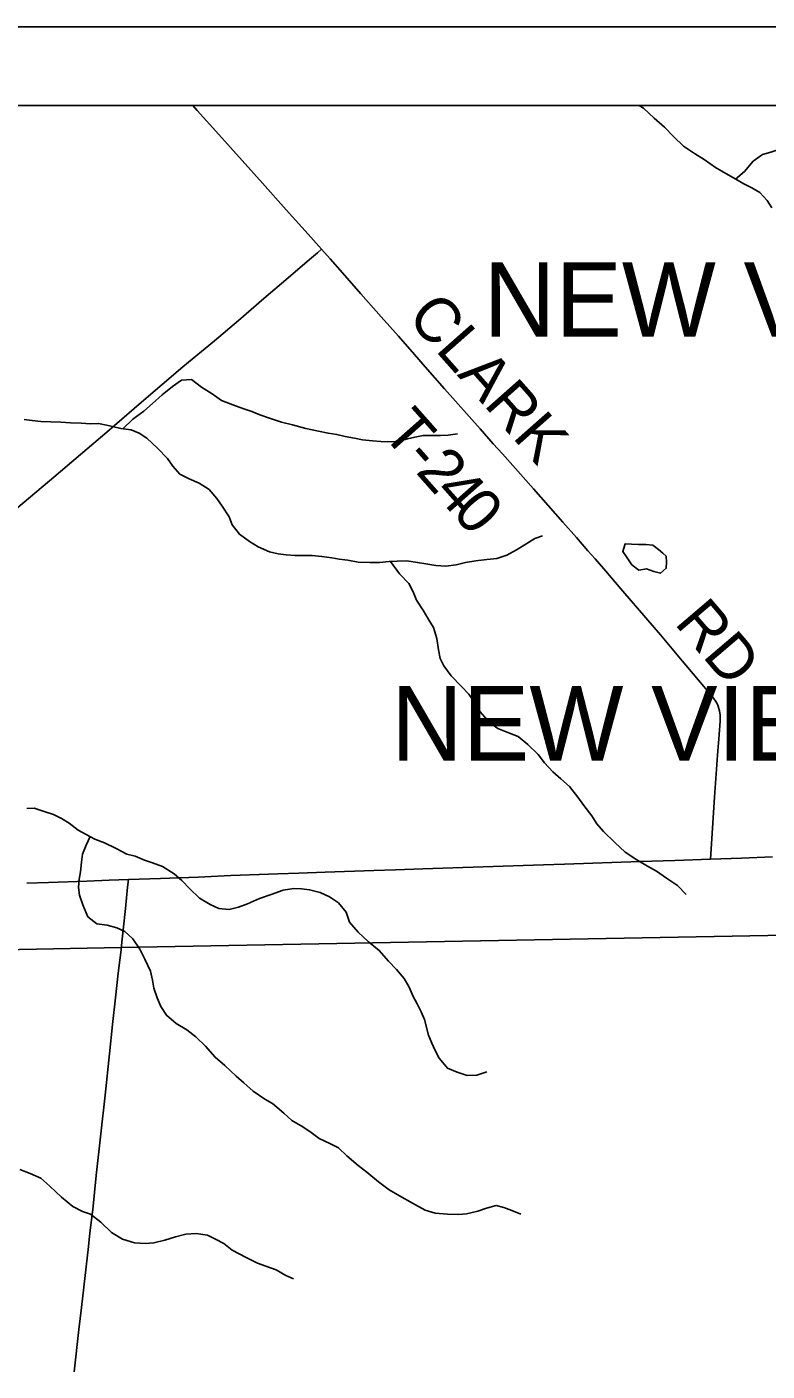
# Model space of a CAD drawing. Extents: x 0 to 48.6, y 0 to 22.
# Drawn here: x 7.09 to 8.031, y 19.291 to 21 of the extents above; entities that cross this region are included whole.
import ezdxf

# ---------------------------------------------------------------- set-up
doc = ezdxf.new("R2010")
doc.units = 0
for name, color, linetype in [('GM_X_Corporation', 7, 'Continuous'), ('GM_X_Corporation_Text', 7, 'Continuous'), ('GM_X_Major_River', 7, 'Continuous'), ('GM_X_Minor_Lake', 7, 'Continuous'), ('GM_X_Minor_River', 7, 'Continuous'), ('GM_X_Rail_Line', 7, 'Continuous'), ('GM_X_State_Route', 7, 'Continuous'), ('GM_X_Township_Road', 7, 'Continuous'), ('GM_X_Township_Road_Text', 7, 'Continuous'), ('SH_Data', 7, 'Continuous')]:
    doc.layers.add(name, color=color, linetype=linetype)

msp = doc.modelspace()

# ---------------------------------------------------------------- linework, layer by layer
at = {"layer": 'GM_X_Corporation'}
msp.add_lwpolyline([(6.9471, 18.0777), (7.2261, 18.2847), (8.5348, 19.2897), (8.9, 19.5692), (8.9, 20.9), (2.1, 20.9)], dxfattribs=at)
msp.add_lwpolyline([(8.9, 19.5692), (8.9, 20.9), (5.795, 20.9), (5.8236, 20.7829), (6.0412, 19.8859), (6.2759, 18.9159), (6.3396, 18.6531), (6.4996, 17.9212), (6.5365, 17.7727), (6.9471, 18.0777), (7.2261, 18.2847), (8.5348, 19.2897)], close=True, dxfattribs=at)
at = {"layer": 'GM_X_Major_River'}
msp.add_lwpolyline([(7.868, 20.9), (7.8738, 20.8966), (7.8873, 20.8839), (7.9004, 20.8723), (7.912, 20.8604), (7.9247, 20.8485), (7.9386, 20.8388), (7.9506, 20.8315), (7.9653, 20.821), (7.9784, 20.8137), (7.9909, 20.8063), (8.0014, 20.8005), (8.0112, 20.7954), (8.0217, 20.7896), (8.0307, 20.7792), (8.0366, 20.7697)], dxfattribs=at)
at = {"layer": 'GM_X_Minor_Lake'}
for points in [[(7.8982, 20.3308), (7.8929, 20.3356), (7.8854, 20.3409), (7.8766, 20.3418), (7.8675, 20.3419), (7.8584, 20.3423), (7.8505, 20.3428), (7.8473, 20.3329), (7.852, 20.3261)], [(7.852, 20.3261), (7.8589, 20.3158), (7.8676, 20.3092), (7.8775, 20.311), (7.887, 20.3075), (7.8953, 20.3052), (7.9025, 20.3116), (7.903, 20.3192), (7.9023, 20.3271), (7.8982, 20.3308)]]:
    msp.add_lwpolyline(points, dxfattribs=at)
at = {"layer": 'GM_X_Minor_River'}
for points in [[(7.9905, 20.8065), (8.002, 20.8162), (8.0131, 20.8294), (8.0249, 20.8376), (8.0356, 20.8406), (8.0478, 20.845), (8.0577, 20.8487), (8.0679, 20.8532), (8.0778, 20.8565), (8.0885, 20.8598), (8.1022, 20.8639), (8.114, 20.868), (8.1254, 20.8728), (8.1369, 20.8791), (8.1483, 20.8847), (8.1601, 20.893), (8.1675, 20.9)], [(7.212, 20.489), (7.2247, 20.501), (7.2384, 20.5115), (7.2495, 20.5209), (7.2618, 20.5322), (7.2748, 20.5427), (7.2862, 20.5509), (7.2991, 20.5516), (7.3119, 20.542), (7.3255, 20.5335), (7.3372, 20.525), (7.3516, 20.5192), (7.3644, 20.5149), (7.3758, 20.511), (7.386, 20.5068), (7.3981, 20.5025), (7.4136, 20.4974), (7.4276, 20.4939), (7.4446, 20.4892), (7.4605, 20.486), (7.4727, 20.4832), (7.4837, 20.4816), (7.4946, 20.4792), (7.5064, 20.4768), (7.5166, 20.4748), (7.5291, 20.4736), (7.5397, 20.4727), (7.553, 20.4722), (7.5625, 20.4733), (7.5735, 20.4762), (7.583, 20.4784), (7.5937, 20.4802), (7.6043, 20.4805), (7.6157, 20.4804), (7.6252, 20.4807), (7.6373, 20.4825)], [(7.0865, 20.5008), (7.0964, 20.4995), (7.1074, 20.4983), (7.1203, 20.4978), (7.1328, 20.4973), (7.1453, 20.4964), (7.159, 20.4959), (7.1707, 20.4954), (7.181, 20.4957), (7.1931, 20.4933), (7.2094, 20.4894), (7.2223, 20.4874), (7.2325, 20.4835), (7.2423, 20.4769), (7.2558, 20.4643), (7.2686, 20.4513), (7.2754, 20.4414), (7.2844, 20.4314), (7.2961, 20.4252), (7.3089, 20.4198), (7.3214, 20.4117), (7.3311, 20.4002), (7.3379, 20.3907), (7.3469, 20.3769), (7.3509, 20.3667), (7.36, 20.3548), (7.3728, 20.3456), (7.3837, 20.339), (7.3981, 20.3325), (7.4091, 20.3301), (7.4193, 20.3288), (7.4307, 20.328), (7.4527, 20.3278), (7.4648, 20.3265), (7.4773, 20.3249), (7.4868, 20.3233), (7.4978, 20.3217), (7.511, 20.3193), (7.5258, 20.3188), (7.538, 20.319), (7.5505, 20.3201), (7.5607, 20.3207), (7.5729, 20.321), (7.5865, 20.319), (7.5971, 20.317), (7.6096, 20.315), (7.6225, 20.3141), (7.6355, 20.3159), (7.6476, 20.3188), (7.6605, 20.321), (7.6746, 20.3227), (7.6871, 20.3241), (7.7001, 20.3282), (7.7123, 20.3349), (7.7218, 20.3409), (7.7356, 20.3495), (7.7454, 20.3528)], [(7.5519, 20.3202), (7.5633, 20.3044), (7.5753, 20.2921), (7.5809, 20.2815), (7.5853, 20.2708), (7.5939, 20.2574), (7.5999, 20.2471), (7.6067, 20.2364), (7.6111, 20.2224), (7.6129, 20.2079), (7.615, 20.1969), (7.6199, 20.1874), (7.6293, 20.1747), (7.642, 20.1617), (7.6518, 20.1514), (7.6586, 20.1415), (7.666, 20.1289), (7.6777, 20.1155), (7.6886, 20.1078), (7.7034, 20.102), (7.7143, 20.0977), (7.7267, 20.0873), (7.7399, 20.0747), (7.7478, 20.064), (7.7583, 20.0529), (7.7685, 20.0437), (7.7798, 20.0341), (7.7903, 20.0203), (7.7978, 20.01), (7.8079, 19.9966), (7.8143, 19.9867), (7.8229, 19.9768), (7.8372, 19.963), (7.8504, 19.9507), (7.8651, 19.9407), (7.8787, 19.9326), (7.8904, 19.9264), (7.9028, 19.9176), (7.9168, 19.908), (7.928, 19.8965)], [(7.0897, 20.0062), (7.0992, 20.0065), (7.112, 20.0022), (7.1238, 19.9983), (7.134, 19.9933), (7.1438, 19.9875), (7.1551, 19.9783), (7.1653, 19.9729), (7.1762, 19.9671), (7.1887, 19.9624), (7.2034, 19.9554), (7.2167, 19.9481), (7.2276, 19.9453), (7.2394, 19.9403), (7.2496, 19.9368), (7.2624, 19.9325), (7.2772, 19.9229), (7.2869, 19.9144), (7.2971, 19.9041), (7.3091, 19.8922), (7.3227, 19.8841), (7.3337, 19.8791), (7.3469, 19.8775), (7.3587, 19.8808), (7.3702, 19.8848), (7.3854, 19.8915), (7.4002, 19.8967), (7.4155, 19.9023), (7.4291, 19.9044), (7.439, 19.904), (7.4492, 19.9027), (7.4625, 19.8992), (7.4746, 19.8938), (7.4859, 19.8861), (7.4957, 19.8742), (7.5001, 19.8617), (7.511, 19.8487), (7.5242, 19.8364), (7.5377, 19.8256), (7.5497, 19.8119), (7.5595, 19.8012), (7.5693, 19.7897), (7.5756, 19.779), (7.5808, 19.7672), (7.5861, 19.7576), (7.5909, 19.7477), (7.5954, 19.7378), (7.6005, 19.718), (7.6046, 19.7078), (7.6087, 19.6982), (7.6139, 19.6887), (7.6244, 19.6757), (7.6369, 19.6706), (7.6494, 19.6667), (7.6619, 19.667), (7.6745, 19.6711)], [(7.1701, 19.9703), (7.1652, 19.9596), (7.1605, 19.9478), (7.1593, 19.938), (7.158, 19.9255), (7.1564, 19.916), (7.1556, 19.9054), (7.1566, 19.8959), (7.1611, 19.8837), (7.1674, 19.8685), (7.1787, 19.8596), (7.192, 19.8576), (7.2044, 19.8545), (7.2143, 19.8498), (7.2244, 19.8402), (7.2334, 19.8273), (7.2398, 19.8143), (7.2472, 19.7994), (7.2494, 19.7876), (7.2512, 19.7778), (7.2556, 19.7652), (7.2601, 19.7541), (7.2672, 19.7431), (7.2796, 19.7327), (7.2932, 19.7246), (7.3045, 19.7158), (7.3169, 19.7039), (7.329, 19.6898), (7.3414, 19.6794), (7.3557, 19.6656), (7.3658, 19.6572), (7.3775, 19.6464), (7.3922, 19.6364), (7.402, 19.631), (7.4164, 19.6187), (7.4265, 19.6095), (7.4405, 19.6014), (7.4514, 19.5941), (7.4616, 19.5865), (7.4748, 19.5799), (7.4858, 19.5745), (7.4967, 19.5645), (7.511, 19.5522), (7.5219, 19.5438), (7.537, 19.5315), (7.5502, 19.5211), (7.5634, 19.5134), (7.58, 19.5042), (7.5963, 19.4953), (7.6087, 19.4914), (7.6247, 19.4901), (7.6387, 19.4896), (7.6486, 19.4906), (7.663, 19.4939), (7.6741, 19.498), (7.6862, 19.5013), (7.6961, 19.4986), (7.7063, 19.495), (7.7176, 19.4904)], [(7.0811, 19.547), (7.0939, 19.542), (7.1075, 19.5361), (7.1192, 19.5258), (7.1339, 19.512), (7.1482, 19.5001), (7.1606, 19.4935), (7.1709, 19.49), (7.184, 19.48), (7.1976, 19.467), (7.2112, 19.4585), (7.2267, 19.4538), (7.2403, 19.453), (7.2514, 19.4536), (7.2654, 19.4573), (7.2787, 19.4613), (7.2917, 19.4646), (7.305, 19.4657), (7.3194, 19.4633), (7.3296, 19.4586), (7.3401, 19.4528), (7.3507, 19.4444), (7.3684, 19.4351), (7.3832, 19.4281), (7.3938, 19.4239), (7.4066, 19.4192), (7.4191, 19.4122), (7.4289, 19.408)]]:
    msp.add_lwpolyline(points, dxfattribs=at)
at = {"layer": 'GM_X_Rail_Line'}
msp.add_lwpolyline([(2.1, 19.7643), (2.1011, 19.7645), (2.172, 19.7738), (2.2311, 19.7779), (2.3038, 19.7803), (2.4027, 19.7791), (2.7583, 19.782), (3.4579, 19.785), (4.2295, 19.785), (4.6206, 19.7852), (5.0462, 19.7937), (5.6922, 19.8043), (6.0216, 19.8102), (6.7352, 19.82), (7.2096, 19.8291), (8.1004, 19.8459), (8.9, 19.8619)], dxfattribs=at)
at = {"layer": 'GM_X_State_Route'}
msp.add_lwpolyline([(7.0896, 19.911), (7.1175, 19.912), (7.166, 19.9137), (7.1945, 19.915), (7.219, 19.9158), (7.2597, 19.9172), (7.3075, 19.9189), (7.3491, 19.9208), (7.4087, 19.9228), (7.4354, 19.9237), (7.4689, 19.9249), (7.531, 19.9274), (7.5583, 19.928), (7.5931, 19.9294), (7.708, 19.9333), (7.7465, 19.9345), (7.7732, 19.9354), (7.8694, 19.9388), (7.9135, 19.9401), (7.9587, 19.9417), (7.9981, 19.9429), (8.0378, 19.9444)], dxfattribs=at)
at = {"layer": 'GM_X_Township_Road'}
for points in [[(7.4645, 20.7172), (7.4474, 20.7365), (7.4194, 20.7673), (7.3892, 20.8011), (7.3637, 20.83), (7.3338, 20.8633), (7.3064, 20.8938), (7.3009, 20.9)], [(7.0538, 20.3683), (7.1242, 20.4276), (7.1833, 20.4779), (7.1913, 20.4848), (7.2012, 20.4933), (7.2356, 20.5229), (7.2882, 20.5675), (7.3283, 20.6009), (7.3587, 20.6265), (7.3911, 20.6545), (7.4218, 20.6808), (7.4492, 20.7042), (7.4591, 20.7127), (7.4645, 20.7172)], [(7.9587, 19.9417), (7.9641, 20.0206), (7.9677, 20.074), (7.9681, 20.0792), (7.9685, 20.0845), (7.9689, 20.0894), (7.9694, 20.0943), (7.9699, 20.1), (7.971, 20.1173), (7.9711, 20.121), (7.9711, 20.1248), (7.9704, 20.1303), (7.9692, 20.1345), (7.9681, 20.1374), (7.9669, 20.1398), (7.9655, 20.1423), (7.9626, 20.1463), (7.9588, 20.1512), (7.9503, 20.1612), (7.9366, 20.1772), (7.9227, 20.194), (7.8951, 20.2268), (7.8768, 20.2487), (7.8476, 20.2826), (7.8233, 20.3109), (7.8122, 20.3235), (7.803, 20.3336), (7.7885, 20.3506), (7.7712, 20.3701), (7.7338, 20.4125), (7.6943, 20.4572), (7.6825, 20.47), (7.6662, 20.4888), (7.6209, 20.5399), (7.5962, 20.5679), (7.5826, 20.5832), (7.5621, 20.6065), (7.5402, 20.6311), (7.5144, 20.6606), (7.491, 20.6871), (7.4755, 20.7049), (7.4645, 20.7172)], [(7.15, 19.2899), (7.1561, 19.3436), (7.1592, 19.3714), (7.1681, 19.4491), (7.17, 19.4664), (7.1735, 19.496), (7.1779, 19.5393), (7.1838, 19.5924), (7.1892, 19.6417), (7.1948, 19.6942), (7.1987, 19.7313), (7.2026, 19.7653), (7.2059, 19.7967), (7.2096, 19.8263), (7.2105, 19.8362), (7.2151, 19.8788), (7.2179, 19.9059), (7.219, 19.9158)]]:
    msp.add_lwpolyline(points, dxfattribs=at)
at = {"layer": 'SH_Data'}
for p, q in [((2, 21), (9, 21)), ((2.1, 20.9), (8.9, 20.9))]:
    msp.add_line(p, q, dxfattribs=at)

# ---------------------------------------------------------------- texts
at = {"layer": 'GM_X_Corporation_Text'}
for p in [(7.6702, 20.606), (7.5527, 20.0671)]:
    msp.add_text('NEW VIENNA', height=0.0947, rotation=0, dxfattribs=at).set_placement(p)
at = {"layer": 'GM_X_Township_Road_Text'}
for s, height, rotation, p in [('CLARK', 0.05682, 311.4833, (7.5717, 20.63)), ('T', 0.0568, 311.4785, (7.5396, 20.483)), ('-', 0.0568, 311.4787, (7.5677, 20.4512)), ('2', 0.0568, 311.4785, (7.583, 20.4339)), ('4', 0.0568, 311.476, (7.606, 20.4079)), ('0', 0.0568, 311.4642, (7.629, 20.3819)), ('RD', 0.05682, 310.4399, (7.9119, 20.2415))]:
    msp.add_text(s, height=height, rotation=rotation, dxfattribs=at).set_placement(p)

doc.saveas('drawing.dxf')
